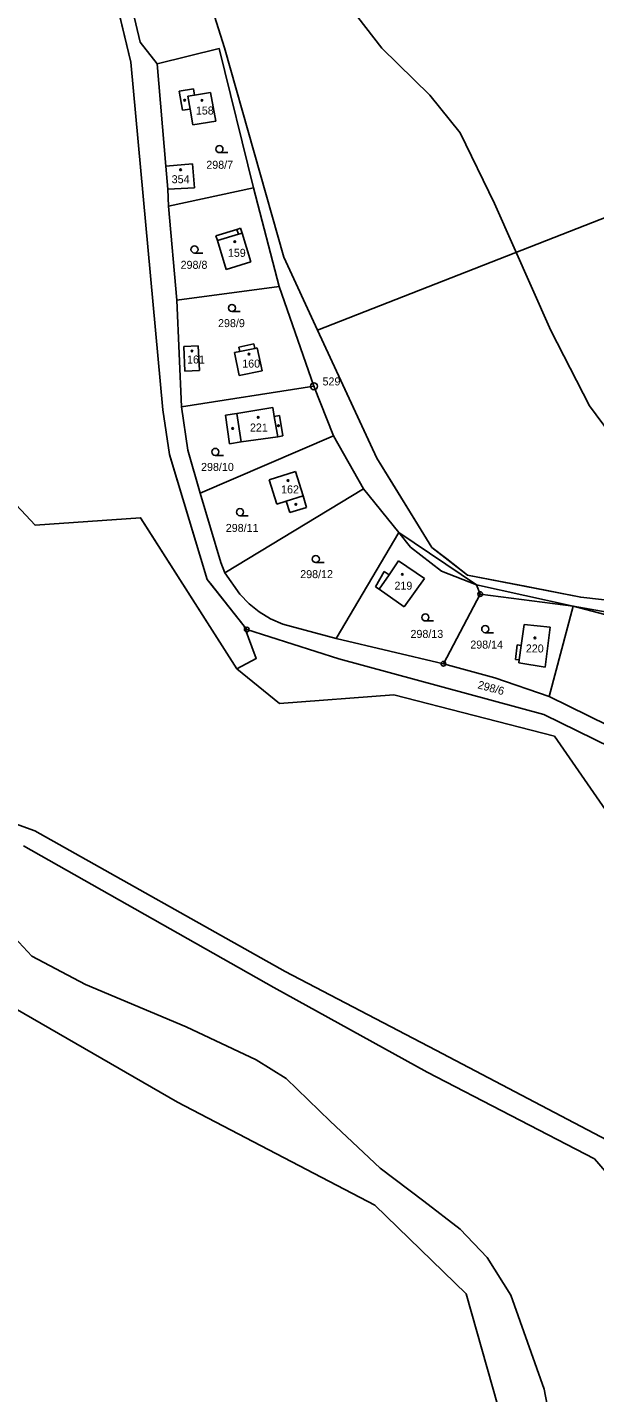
# Model space of a CAD drawing. Extents: x -725765 to -723182, y -1052705 to -1049154.
# Drawn here: x -724049.7 to -723929.1, y -1051385.7 to -1051095.6 of the extents above; entities that cross this region are included whole.
import ezdxf

# ---------------------------------------------------------------- set-up
doc = ezdxf.new("R2010")
doc.units = 0
for name, color, linetype in [('Vrstva 1', 7, 'Continuous'), ('Vrstva 17', 7, 'Continuous'), ('Vrstva 18', 7, 'Continuous'), ('Vrstva 19', 7, 'Continuous'), ('Vrstva 25', 7, 'Continuous'), ('Vrstva 4', 7, 'Continuous'), ('Vrstva 52', 7, 'Continuous')]:
    doc.layers.add(name, color=color, linetype=linetype)

msp = doc.modelspace()

# ---------------------------------------------------------------- linework, layer by layer
at = {"layer": 'Vrstva 1'}
for points in [[(-724039.77, -1051039.14), (-724025.69, -1051098.73)], [(-724014.49, -1051078.55), (-724007.77, -1051099.92)], [(-724027.68, -1051103.02), (-724033.1, -1051080.16)], [(-723823.99, -1051095.79), (-723987.97, -1051159.94)], [(-724025.69, -1051098.73), (-724022.06, -1051103.32)], [(-724022.06, -1051103.32), (-724008.86, -1051100.12)], [(-724008.86, -1051100.12), (-724001.57, -1051129.67)], [(-724007.77, -1051099.92), (-723995.17, -1051144.41)], [(-724020.83, -1051176.88), (-724027.68, -1051103.02)], [(-724022.06, -1051103.32), (-724020.21, -1051125.07)], [(-724017.36, -1051109.18), (-724014.36, -1051108.65)], [(-724017.36, -1051109.18), (-724016.67, -1051113.23)], [(-724014.36, -1051108.65), (-724014.13, -1051109.99)], [(-724014.13, -1051109.99), (-724010.71, -1051109.42)], [(-724010.71, -1051109.42), (-724009.59, -1051115.5)], [(-724016.67, -1051113.23), (-724015.06, -1051112.97)], [(-724015.06, -1051112.97), (-724014.47, -1051116.31)], [(-724014.47, -1051116.31), (-724009.59, -1051115.5)], [(-724020.21, -1051125.07), (-724014.55, -1051124.63)], [(-724014.55, -1051124.63), (-724014.14, -1051129.67)], [(-724020.21, -1051125.07), (-724019.81, -1051129.99)], [(-724019.81, -1051129.99), (-724014.14, -1051129.67)], [(-724019.81, -1051129.99), (-724019.65, -1051133.57)], [(-724019.65, -1051133.57), (-724001.57, -1051129.67)], [(-724001.57, -1051129.67), (-723996.1, -1051150.68)], [(-724019.65, -1051133.57), (-724017.89, -1051153.54)], [(-724009.58, -1051139.88), (-724005.1, -1051138.52)], [(-724005.1, -1051138.52), (-724004.32, -1051138.28)], [(-724004.32, -1051138.28), (-724004.01, -1051139.31)], [(-724004.01, -1051139.31), (-724002.18, -1051145.41)], [(-724009.58, -1051139.88), (-724009.27, -1051140.89)], [(-724009.27, -1051140.89), (-724007.4, -1051147.04)], [(-723995.17, -1051144.41), (-723987.97, -1051159.94)], [(-724007.4, -1051147.04), (-724002.18, -1051145.41)], [(-724017.89, -1051153.54), (-723996.1, -1051150.68)], [(-723996.1, -1051150.68), (-723988.74, -1051171.87)], [(-724017.89, -1051153.54), (-724016.87, -1051176.26)], [(-723987.97, -1051159.94), (-723975.36, -1051187.14)], [(-724016.41, -1051163.4), (-724013.32, -1051163.25)], [(-724016.41, -1051163.4), (-724016.16, -1051168.69)], [(-724013.32, -1051163.25), (-724013.07, -1051168.54)], [(-724005.65, -1051164.69), (-724004.48, -1051164.46)], [(-724005.65, -1051164.69), (-724004.62, -1051169.56)], [(-724004.68, -1051163.53), (-724001.5, -1051162.88)], [(-724004.68, -1051163.53), (-724004.48, -1051164.46)], [(-724001.5, -1051162.88), (-724001.33, -1051163.84)], [(-724001.33, -1051163.84), (-724000.79, -1051163.73)], [(-724000.79, -1051163.73), (-723999.74, -1051168.56)], [(-724016.16, -1051168.69), (-724013.07, -1051168.54)], [(-724004.62, -1051169.56), (-723999.74, -1051168.56)], [(-724016.87, -1051176.26), (-723988.74, -1051171.87)], [(-723988.74, -1051171.87), (-723984.61, -1051182.4)], [(-724048.01, -1051201.39), (-724071.19, -1051176.65)], [(-724019.48, -1051186.39), (-724020.83, -1051176.88)], [(-724016.87, -1051176.26), (-724015.52, -1051185.45)], [(-724005.15, -1051177.64), (-723997.47, -1051176.4)], [(-723997.47, -1051176.4), (-723997.16, -1051178.26)], [(-724007.57, -1051178.03), (-724005.15, -1051177.64)], [(-724007.57, -1051178.03), (-724006.68, -1051184.08)], [(-723997.16, -1051178.26), (-723996.08, -1051178.08)], [(-723996.08, -1051178.08), (-723995.38, -1051182.38)], [(-724012.92, -1051194.58), (-723984.61, -1051182.4)], [(-724004.18, -1051183.71), (-723996.45, -1051182.58)], [(-723996.45, -1051182.58), (-723995.38, -1051182.38)], [(-723984.61, -1051182.4), (-723978.21, -1051193.69)], [(-724015.52, -1051185.45), (-724012.92, -1051194.58)], [(-724006.68, -1051184.08), (-724004.18, -1051183.71)], [(-724011.43, -1051212.92), (-724019.48, -1051186.39)], [(-723975.36, -1051187.14), (-723963.68, -1051206.1)], [(-723998.27, -1051191.73), (-723992.63, -1051190)], [(-723992.63, -1051190), (-723991.02, -1051195.16)], [(-724012.92, -1051194.58), (-724008.56, -1051209.35)], [(-724007.67, -1051211.48), (-723978.21, -1051193.69)], [(-723998.27, -1051191.73), (-723996.64, -1051196.89)], [(-723978.21, -1051193.69), (-723970.69, -1051202.93)], [(-723996.64, -1051196.89), (-723994.62, -1051196.27)], [(-723994.62, -1051196.27), (-723993.88, -1051198.7)], [(-723991.02, -1051195.16), (-723990.35, -1051197.66)], [(-724025.58, -1051199.82), (-724048.01, -1051201.39)], [(-724005.11, -1051231.9), (-724025.58, -1051199.82)], [(-723993.88, -1051198.7), (-723990.35, -1051197.66)], [(-723983.99, -1051225.47), (-723970.69, -1051202.93)], [(-723970.69, -1051202.93), (-723954.16, -1051214.05)], [(-723963.68, -1051206.1), (-723956.11, -1051212)], [(-723972.78, -1051211.92), (-723970.74, -1051208.94)], [(-723970.74, -1051208.94), (-723965.24, -1051212.72)], [(-724008.56, -1051209.35), (-724007.67, -1051211.48)], [(-724007.67, -1051211.48), (-724004.49, -1051216.07)], [(-723975.63, -1051214.47), (-723973.79, -1051211.24)], [(-723973.79, -1051211.24), (-723972.78, -1051211.92)], [(-723956.11, -1051212), (-723932.03, -1051216.69)], [(-724003.58, -1051222.85), (-724011.43, -1051212.92)], [(-723975.63, -1051214.47), (-723974.88, -1051215)], [(-723969.57, -1051218.77), (-723965.24, -1051212.72)], [(-723954.16, -1051214.05), (-723953.39, -1051216.03)], [(-724004.49, -1051216.07), (-724002.53, -1051218.07)], [(-723974.88, -1051215), (-723969.57, -1051218.77)], [(-723961.22, -1051230.84), (-723953.39, -1051216.03)], [(-723953.39, -1051216.03), (-723933.66, -1051218.62)], [(-723932.03, -1051216.69), (-723906.25, -1051219.62)], [(-724002.53, -1051218.07), (-724000.4, -1051219.8)], [(-724000.4, -1051219.8), (-723997.97, -1051221.32)], [(-723938.77, -1051237.82), (-723933.66, -1051218.62)], [(-723933.66, -1051218.62), (-723903.51, -1051223.9)], [(-723933.66, -1051218.62), (-723905.09, -1051226.09)], [(-724003.58, -1051222.85), (-724001, -1051229.73)], [(-724003.02, -1051223.56), (-724003.58, -1051222.85)], [(-723983.42, -1051229.78), (-724003.02, -1051223.56)], [(-723997.97, -1051221.32), (-723995.35, -1051222.43)], [(-723995.35, -1051222.43), (-723983.99, -1051225.47)], [(-723944.67, -1051226.97), (-723944.05, -1051222.51)], [(-723944.05, -1051222.51), (-723938.51, -1051223.04)], [(-723939.59, -1051231.56), (-723938.51, -1051223.04)], [(-723983.99, -1051225.47), (-723961.22, -1051230.84)], [(-723945.86, -1051229.91), (-723945.53, -1051226.82)], [(-723945.53, -1051226.82), (-723944.67, -1051226.97)], [(-724001, -1051229.73), (-724005.11, -1051231.9)], [(-723996.05, -1051239.31), (-724005.11, -1051231.9)], [(-723939.88, -1051241.6), (-723983.42, -1051229.78)], [(-723961.22, -1051230.84), (-723950.27, -1051233.8)], [(-723945.86, -1051229.91), (-723945.09, -1051230.03)], [(-723945.18, -1051230.67), (-723945.09, -1051230.03)], [(-723945.18, -1051230.67), (-723939.59, -1051231.56)], [(-723950.27, -1051233.8), (-723938.77, -1051237.82)], [(-723971.78, -1051237.47), (-723996.05, -1051239.31)], [(-723937.57, -1051246.22), (-723971.78, -1051237.47)], [(-723938.77, -1051237.82), (-723926.16, -1051243.94)], [(-723922.07, -1051250.33), (-723939.88, -1051241.6)], [(-723911.28, -1051284.18), (-723937.57, -1051246.22)], [(-724048.1, -1051266.31), (-724052.94, -1051264.55)], [(-723994.84, -1051296.21), (-724048.1, -1051266.31)], [(-723997.26, -1051299.64), (-724050.47, -1051269.54)], [(-724017.73, -1051324.02), (-724066.55, -1051295.85)], [(-723962.81, -1051312.97), (-723994.84, -1051296.21)], [(-723964.68, -1051317.59), (-723997.26, -1051299.64)], [(-723962.81, -1051312.97), (-723926.39, -1051332.1)], [(-723929.12, -1051336.03), (-723964.68, -1051317.59)], [(-723975.76, -1051345.87), (-724017.73, -1051324.02)], [(-723916.43, -1051350.67), (-723929.12, -1051336.03)], [(-723956.41, -1051364.73), (-723975.76, -1051345.87)], [(-723944.12, -1051407.98), (-723956.41, -1051364.73)]]:
    msp.add_lwpolyline(points, dxfattribs=at)
at = {"layer": 'Vrstva 25'}
for points in [[(-724008.83, -1051122.22), (-724007.08, -1051122.22)], [(-724014.13, -1051143.55), (-724012.38, -1051143.55)], [(-724006.17, -1051155.99), (-724004.42, -1051155.99)], [(-724009.71, -1051186.56), (-724007.96, -1051186.56)], [(-724004.46, -1051199.37), (-724002.71, -1051199.37)], [(-723988.34, -1051209.34), (-723986.59, -1051209.34)], [(-723965.05, -1051221.74), (-723963.3, -1051221.74)], [(-723952.33, -1051224.23), (-723950.58, -1051224.23)]]:
    msp.add_lwpolyline(points, dxfattribs=at)
for centre, radius in [((-724016.21, -1051111.08), 0.175), ((-724012.52, -1051111.12), 0.175), ((-724008.83, -1051121.47), 0.75), ((-724017.09, -1051125.87), 0.175), ((-724014.13, -1051142.8), 0.75), ((-724005.57, -1051141.13), 0.175), ((-724006.17, -1051155.24), 0.75), ((-724014.65, -1051164.39), 0.175), ((-724002.53, -1051165.03), 0.175), ((-723988.74, -1051171.87), 0.75), ((-723988.74, -1051171.87), 0.032), ((-724000.59, -1051178.48), 0.175), ((-723996.29, -1051180.24), 0.175), ((-724006, -1051180.83), 0.175), ((-724009.71, -1051185.81), 0.75), ((-723994.27, -1051191.9), 0.175), ((-723992.58, -1051196.96), 0.175), ((-724004.46, -1051198.62), 0.75), ((-723988.34, -1051208.59), 0.75), ((-723969.96, -1051211.83), 0.175), ((-723953.39, -1051216.03), 0.5), ((-723953.39, -1051216.03), 0.032), ((-723965.05, -1051220.99), 0.75), ((-724003.02, -1051223.56), 0.5), ((-724003.02, -1051223.56), 0.032), ((-723952.33, -1051223.48), 0.75), ((-723941.78, -1051225.34), 0.175), ((-723961.22, -1051230.84), 0.5), ((-723961.22, -1051230.84), 0.032)]:
    msp.add_circle(centre, radius, dxfattribs=at)
at = {"layer": 'Vrstva 4'}
for points in [[(-724015.55, -1051110.22), (-724014.13, -1051109.99)], [(-724015.55, -1051110.22), (-724015.06, -1051112.97)], [(-724005.1, -1051138.52), (-724004.79, -1051139.55)], [(-724004.79, -1051139.55), (-724004.01, -1051139.31)], [(-724009.27, -1051140.89), (-724004.79, -1051139.55)], [(-724004.48, -1051164.46), (-724001.33, -1051163.84)], [(-724005.15, -1051177.64), (-724004.18, -1051183.71)], [(-723997.16, -1051178.26), (-723996.45, -1051182.58)], [(-723994.62, -1051196.27), (-723991.02, -1051195.16)], [(-723970.69, -1051202.93), (-723968.24, -1051206.03)], [(-723968.24, -1051206.03), (-723961.65, -1051211.13)], [(-723974.88, -1051215), (-723972.78, -1051211.92)], [(-723961.65, -1051211.13), (-723954.16, -1051214.05)], [(-723954.16, -1051214.05), (-723933.66, -1051218.62)], [(-723945.09, -1051230.03), (-723944.67, -1051226.97)]]:
    msp.add_lwpolyline(points, dxfattribs=at)
at = {"layer": 'Vrstva 52'}
for points in [[(-723864.69, -1051239.39), (-723871.17, -1051242.92), (-723884.57, -1051232.17), (-723903.51, -1051223.9), (-723933.66, -1051218.62), (-723953.39, -1051216.03), (-723954.16, -1051214.05), (-723970.69, -1051202.93), (-723978.21, -1051193.69), (-723984.61, -1051182.4), (-723988.74, -1051171.87), (-723996.1, -1051150.68), (-724001.57, -1051129.67), (-724008.86, -1051100.12), (-724022.06, -1051103.32), (-724025.69, -1051098.73), (-724039.77, -1051039.14)], [(-724014.49, -1051078.55), (-724007.77, -1051099.92), (-723995.17, -1051144.41), (-723987.97, -1051159.94), (-723978.1, -1051181.23), (-723975.36, -1051187.14), (-723972.06, -1051192.5), (-723963.68, -1051206.1), (-723960.51, -1051208.57), (-723956.11, -1051212), (-723943.51, -1051214.45), (-723932.03, -1051216.69), (-723906.25, -1051219.62), (-723899.8, -1051220.8), (-723881.61, -1051224.12)], [(-723982.81, -1051089), (-723974.31, -1051100), (-723964.13, -1051110), (-723957.63, -1051118), (-723950.38, -1051133), (-723938.38, -1051160), (-723930.19, -1051176), (-723919.81, -1051190), (-723910.69, -1051200), (-723901.88, -1051208), (-723883.81, -1051222), (-723881.61, -1051224.12)], [(-724030.47, -1051091.27), (-724027.68, -1051103.02), (-724020.83, -1051176.88), (-724019.48, -1051186.39), (-724019.11, -1051187.59), (-724011.43, -1051212.92), (-724010.76, -1051213.77), (-724003.58, -1051222.85)], [(-724003.58, -1051222.85), (-724001, -1051229.73), (-724005.11, -1051231.9), (-724024.82, -1051201.01), (-724025.58, -1051199.82), (-724048.01, -1051201.39), (-724071.19, -1051176.65)], [(-723706.54, -1051486.44), (-723767.94, -1051481.2), (-723772.04, -1051474.32), (-723782.91, -1051472.84), (-723791.24, -1051477.29), (-723804.04, -1051459.34), (-723805.81, -1051458.83), (-723815.86, -1051443.78), (-723829.05, -1051424.03), (-723834.01, -1051416.11), (-723838.11, -1051406.2), (-723841.35, -1051396.8), (-723855.41, -1051359.31), (-723866.9, -1051326.29), (-723877.25, -1051312.25), (-723881.29, -1051305.27), (-723901.66, -1051268.64), (-723911.76, -1051257.07), (-723922.07, -1051250.33), (-723939.88, -1051241.6), (-723983.42, -1051229.78), (-724003.02, -1051223.56), (-724003.58, -1051222.85)], [(-724052.94, -1051264.55), (-724048.1, -1051266.31), (-723994.84, -1051296.21), (-723962.81, -1051312.97), (-723926.39, -1051332.1), (-723911.42, -1051348.47), (-723895.29, -1051392.3), (-723884.86, -1051418.68), (-723868.34, -1051447.67), (-723828.41, -1051486.92), (-723818.84, -1051492.05), (-723810.19, -1051499.57), (-723787.98, -1051513.89), (-723769.62, -1051527.53), (-723760.44, -1051529.74), (-723735.81, -1051547.23), (-723726.68, -1051549.29), (-723706.61, -1051583.2)], [(-724050.47, -1051269.54), (-723997.26, -1051299.64), (-723964.68, -1051317.59), (-723929.12, -1051336.03), (-723916.43, -1051350.67), (-723899.09, -1051393.61), (-723888.79, -1051420.29), (-723872.12, -1051450.91), (-723831.46, -1051490.09), (-723822.26, -1051497.46), (-723811.9, -1051505.06), (-723789.38, -1051517.54), (-723771.8, -1051531.34), (-723761.92, -1051534.99), (-723738.43, -1051552.03), (-723728.55, -1051554.37), (-723711.06, -1051586.5), (-723687.84, -1051594.09), (-723669.45, -1051611.26), (-723662.6, -1051628), (-723652.76, -1051646.8), (-723641.04, -1051681.92), (-723643.18, -1051682.48), (-723641.32, -1051689.61)], [(-724055.13, -1051286), (-724048.69, -1051293), (-724037.31, -1051299), (-724015.88, -1051308), (-724001, -1051315), (-723994.63, -1051319), (-723985.31, -1051328), (-723974.63, -1051338), (-723965.38, -1051345), (-723957.63, -1051351), (-723951.88, -1051357), (-723946.88, -1051365), (-723939.81, -1051385), (-723930.81, -1051432)]]:
    msp.add_lwpolyline(points, dxfattribs=at)

# ---------------------------------------------------------------- texts
at = {"layer": 'Vrstva 17'}
msp.add_text('529', height=1.7, dxfattribs=at).set_placement((-723986.91, -1051171.69))
at = {"layer": 'Vrstva 18'}
for s, p in [('298/7', (-724011.62, -1051125.65)), ('298/8', (-724017.08, -1051146.91)), ('298/9', (-724009.12, -1051159.3)), ('298/10', (-724012.73, -1051189.86)), ('298/11', (-724007.48, -1051202.82)), ('298/12', (-723991.65, -1051212.64)), ('298/13', (-723968.21, -1051225.34)), ('298/14', (-723955.5, -1051227.61))]:
    msp.add_text(s, height=1.7, dxfattribs=at).set_placement(p)
msp.add_text('298/6', height=1.7, rotation=344.6027, dxfattribs=at).set_placement((-723954.05, -1051236.02))
at = {"layer": 'Vrstva 19'}
for s, p in [('158', (-724013.84, -1051114.12)), ('354', (-724018.98, -1051128.72)), ('159', (-724007.03, -1051144.36)), ('161', (-724015.72, -1051167.03)), ('160', (-724003.98, -1051167.9)), ('221', (-724002.34, -1051181.48)), ('162', (-723995.72, -1051194.63)), ('219', (-723971.62, -1051215.09)), ('220', (-723943.69, -1051228.43))]:
    msp.add_text(s, height=1.7, dxfattribs=at).set_placement(p)

doc.saveas('drawing.dxf')
